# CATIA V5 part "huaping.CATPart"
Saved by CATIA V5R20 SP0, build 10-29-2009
Part number: 花瓶
Material "Sunset"
Material "Water": density 1000 kg/m3
Bounding box of the stored display mesh (mm): x -80 to 80, y -80 to 79.919, z 0 to 221.578
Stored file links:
  C:\Users\DELL\Desktop\huaping.CATPart
  C:\Program Files (x86)\Dassault Systemes\B20\intel_a\startup\materials\Catalog.CATMaterial
  C:\Program Files (x86)\Dassault Systemes\B20\intel_a\startup\materials\sunset.jpg
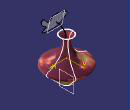
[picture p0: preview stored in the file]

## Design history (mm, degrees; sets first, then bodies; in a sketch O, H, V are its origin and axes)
Body1 (main body), material "Sunset"
  Plane1: type Offset, RefPlane xy-plane, Offset 20
  Set1
    Plane2: type Offset, RefPlane xy-plane, Offset 40 {= Plane1.Offset+`Plane2.相对Offset`}
    Plane3: type Offset, RefPlane xy-plane, Offset 60 {= Plane2.Offset+`Plane3.相对Offset`}
    Plane4: type Offset, RefPlane xy-plane, Offset 80 {= Plane3.Offset+`Plane4.相对Offset`}
    Plane5: type Offset, RefPlane xy-plane, Offset 100 {= Plane4.Offset+`Plane5.相对Offset`}
    Plane6: type Offset, RefPlane xy-plane, Offset 120 {= Plane5.Offset+`Plane6.相对Offset`}
    Plane7: type Offset, RefPlane xy-plane, Offset 140 {= Plane6.Offset+`Plane7.相对Offset`}
    Plane8: type Offset, RefPlane xy-plane, Offset 160 {= Plane7.Offset+`Plane8.相对Offset`}
  Sketch1 on Plane4, origin (0, 0, 80), H (1, 0, 0), V (0, 1, 0)
  Sketch2 on Plane4, origin (0, 0, 80), H (1, 0, 0), V (0, 1, 0)
  Sketch3 on Plane8, origin (0, 0, 160), H (1, 0, 0), V (0, 1, 0)
    circle A1 centre (0, 0) radius 25
  Sketch4 on Plane7, origin (0, 0, 140), H (1, 0, 0), V (0, 1, 0)
    circle A1 centre (0, 0) radius 12
  Sketch5 on Plane6, origin (0, 0, 120), H (1, 0, 0), V (0, 1, 0)
    circle A1 centre (0, 0) radius 15
  Sketch6 on Plane5, origin (0, 0, 100), H (1, 0, 0), V (0, 1, 0)
    circle A1 centre (0, 0) radius 25
  Sketch7 on Plane4, origin (0, 0, 80), H (1, 0, 0), V (0, 1, 0)
    circle A1 centre (0, 0) radius 45
  Sketch8 on Plane3, origin (0, 0, 60), H (1, 0, 0), V (0, 1, 0)
    circle A1 centre (0, 0) radius 80
  Sketch9 on Plane2, origin (0, 0, 40), H (1, 0, 0), V (0, 1, 0)
    circle A1 centre (0, 0) radius 60
  Sketch10 on Plane1, origin (0, 0, 20), H (1, 0, 0), V (0, 1, 0)
    circle A1 centre (0, 0) radius 40
  Sketch11 on xy-plane, origin (0, 0, 0), H (1, 0, 0), V (0, 1, 0)
    circle A1 centre (0, 0) radius 20
    point P1 (20, 0)
    coincidence: A1 P1, P1 H
  Loft1: solid, Sections (Sketch3; Sketch4; Sketch5; Sketch6; Sketch7; Sketch8; Sketch9; Sketch10; Sketch11)
  Shell1: IntOffset 1, Face face of Loft1, ExtOffset 0
Body2, material "Water"
  Sketch12 on yz-plane, origin (0, 0, 0), H (0, 1, 0), V (0, 0, 1)
    axis line L1 (0, 0) -> (0, 191.7666)
    point P2 (0, 66.3799)
    line L2 (0, 66.3799) -> (60.8957, 66.3799)
    line L3 (60.8957, 66.3799) -> (70.5438, 60.5399)
    line L4 (70.5438, 60.5399) -> (20.2357, 5.5759)
    line L5 (20.2357, 5.5759) -> (0, 5.5759)
    point P6 (0, 5.5759)
    vertical: L1 V
    coincidence: P2 L1, P6 L1
    horizontal: L2 H, L5 H
  Shaft1: profile Sketch12, axis Sketch12.L1, angle 360
Body3
  Sketch13 on yz-plane, origin (0, 0, 0), H (0, 1, 0), V (0, 0, 1)
    spline S1 through (-41.4652, 181.9162) (-5.7615, 163.6464) (-26.299, 72.612) (-11.1329, 20.3224) (28.3623, 24.4174)
  Plane9: type Normal, Curve Sketch13, RefPoint vertex of Sketch13
  Sketch14 on Plane9, origin (0, -76.3855, 16.0851), H (-1, 0, 0), V (0, 0.2061, 0.9785)
    circle A1 centre (0, 169.4999) radius 1
    point P1 (0, 169.4999)
    coincidence: P1 V
  Rib1: profile Sketch14, centre curve Sketch13
  Sketch15 on Plane9, origin (0, -76.3855, 16.0851), H (-1, 0, 0), V (0, 0.2061, 0.9785)
    spline S1 through (-20, 200) (10, 200) (40, 180) (20, 160) (-30, 150) (-50, 160) (-40, 170) (-50, 180) (-60, 210) (-40, 190) (-20, 200)
    point P1 (-20, 200)
    point P2 (-20, 200)
    coincidence: P1 P2
  Pad1: profile Sketch15, direction (0, 0.9785, -0.2061), length 1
